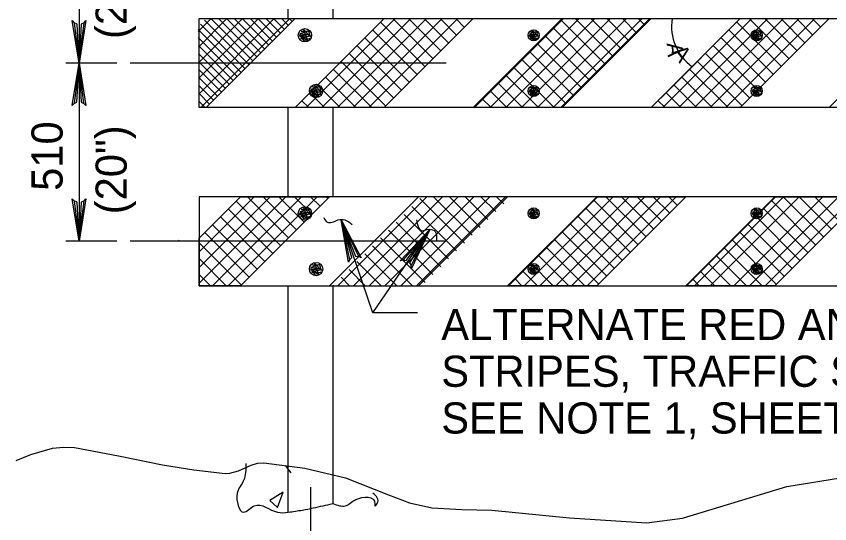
# Model space of a CAD drawing. Extents: x -4 to 901, y -468 to 720.
# Drawn here: x 91 to 178.8, y -333.9 to -279.2 of the extents above; entities that cross this region are included whole.
import ezdxf

# ---------------------------------------------------------------- set-up
doc = ezdxf.new("R2010")
doc.units = 0
doc.layers.add('2', color=7, linetype='Continuous')
doc.layers.add('3', color=7, linetype='Continuous')

msp = doc.modelspace()

# ---------------------------------------------------------------- linework, layer by layer
at = {"layer": '2'}
for p, q in [((97.81975, -265.007625), (97.81975, -284.207625)), ((110.77575, -289.007625), (110.77575, -279.407625)), ((110.77575, -279.407625), (242.46375, -279.407625)), ((111.52375, -289.007625), (121.12375, -279.407625)), ((112.21575, -279.407625), (163.21775, -279.407625)), ((121.12375, -289.007625), (130.72375, -279.407625)), ((130.72375, -289.007625), (140.32375, -279.407625)), ((140.32375, -289.007625), (149.92375, -279.407625)), ((149.92375, -289.007625), (159.52375, -279.407625)), ((159.52375, -289.007625), (169.12375, -279.407625)), ((169.12375, -289.007625), (178.72375, -279.407625)), ((178.72375, -289.007625), (188.32375, -279.407625)), ((122.47175, -281.791625), (122.05975, -280.611625)), ((122.05975, -280.611625), (122.77975, -281.381625)), ((122.77975, -281.381625), (122.56375, -280.683625)), ((147.08375, -281.693625), (146.74175, -280.709625)), ((146.74175, -280.709625), (147.34175, -281.351625)), ((171.14775, -281.693625), (170.80575, -280.709625)), ((170.80575, -280.709625), (171.40575, -281.351625)), ((122.64375, -281.099625), (121.57775, -281.301625)), ((122.08975, -281.791625), (121.57775, -281.135625)), ((121.57775, -281.135625), (122.47175, -281.791625)), ((121.57775, -281.301625), (122.76575, -281.259625)), ((122.45575, -280.761625), (121.62775, -281.043625)), ((121.62775, -281.043625), (122.64375, -281.099625)), ((122.76575, -281.259625), (121.70775, -281.583625)), ((121.70775, -281.583625), (122.68775, -281.561625)), ((121.77975, -280.761625), (122.45575, -280.761625)), ((122.68775, -281.561625), (122.08975, -281.791625)), ((122.17575, -281.207625), (122.17575, -281.207625)), ((122.77575, -281.207625), (122.77575, -281.207625)), ((147.22775, -281.117625), (146.33975, -281.285625)), ((146.76575, -281.693625), (146.33975, -281.147625)), ((146.33975, -281.147625), (147.08375, -281.693625)), ((146.33975, -281.285625), (147.32975, -281.249625)), ((147.07175, -280.835625), (146.38175, -281.069625)), ((146.38175, -281.069625), (147.22775, -281.117625)), ((147.32975, -281.249625), (146.44775, -281.519625)), ((146.44775, -281.519625), (147.26375, -281.501625)), ((146.50775, -280.835625), (147.07175, -280.835625)), ((147.26375, -281.501625), (146.76575, -281.693625)), ((146.83775, -281.207625), (146.83775, -281.207625)), ((146.83775, -281.207625), (146.83775, -281.207625)), ((147.34175, -281.351625), (147.16175, -280.769625)), ((171.29175, -281.117625), (170.40375, -281.285625)), ((170.82975, -281.693625), (170.40375, -281.147625)), ((170.40375, -281.147625), (171.14775, -281.693625)), ((170.40375, -281.285625), (171.39375, -281.249625)), ((171.13575, -280.835625), (170.44575, -281.069625)), ((170.44575, -281.069625), (171.29175, -281.117625)), ((171.39375, -281.249625), (170.51175, -281.519625)), ((170.51175, -281.519625), (171.32775, -281.501625)), ((170.57175, -280.835625), (171.13575, -280.835625)), ((171.32775, -281.501625), (170.82975, -281.693625)), ((170.90175, -281.207625), (170.90175, -281.207625)), ((170.90175, -281.207625), (170.90175, -281.207625)), ((171.40575, -281.351625), (171.22575, -280.769625)), ((101.87775, -284.207625), (96.37975, -284.207625)), ((97.81975, -284.207625), (97.81975, -303.407625)), ((137.40575, -284.207625), (103.31775, -284.207625)), ((160.54175, -287.989625), (164.94775, -283.583625)), ((123.65575, -286.761625), (122.82775, -287.043625)), ((122.97975, -286.761625), (123.65575, -286.761625)), ((123.67175, -287.791625), (123.25975, -286.611625)), ((123.25975, -286.611625), (123.97975, -287.381625)), ((123.97975, -287.381625), (123.76375, -286.683625)), ((147.07175, -286.835625), (146.38175, -287.069625)), ((146.50775, -286.835625), (147.07175, -286.835625)), ((147.08375, -287.693625), (146.74175, -286.709625)), ((146.74175, -286.709625), (147.34175, -287.351625)), ((147.34175, -287.351625), (147.16175, -286.769625)), ((171.13575, -286.835625), (170.44575, -287.069625)), ((170.57175, -286.835625), (171.13575, -286.835625)), ((171.14775, -287.693625), (170.80575, -286.709625)), ((170.80575, -286.709625), (171.40575, -287.351625)), ((171.40575, -287.351625), (171.22575, -286.769625)), ((122.77575, -287.207625), (122.77575, -287.207625)), ((123.84375, -287.099625), (122.77775, -287.301625)), ((123.28975, -287.791625), (122.77775, -287.135625)), ((122.77775, -287.135625), (123.67175, -287.791625)), ((122.77775, -287.301625), (123.96575, -287.259625)), ((122.82775, -287.043625), (123.84375, -287.099625)), ((123.96575, -287.259625), (122.90775, -287.583625)), ((122.90775, -287.583625), (123.88775, -287.561625)), ((123.88775, -287.561625), (123.28975, -287.791625)), ((123.37575, -287.207625), (123.37575, -287.207625)), ((147.22775, -287.117625), (146.33975, -287.285625)), ((146.76575, -287.693625), (146.33975, -287.147625)), ((146.33975, -287.147625), (147.08375, -287.693625)), ((146.33975, -287.285625), (147.32975, -287.249625)), ((146.38175, -287.069625), (147.22775, -287.117625)), ((147.32975, -287.249625), (146.44775, -287.519625)), ((146.44775, -287.519625), (147.26375, -287.501625)), ((147.26375, -287.501625), (146.76575, -287.693625)), ((146.83775, -287.207625), (146.83775, -287.207625)), ((146.83775, -287.207625), (146.83775, -287.207625)), ((171.29175, -287.117625), (170.40375, -287.285625)), ((170.82975, -287.693625), (170.40375, -287.147625)), ((170.40375, -287.147625), (171.14775, -287.693625)), ((170.40375, -287.285625), (171.39375, -287.249625)), ((170.44575, -287.069625), (171.29175, -287.117625)), ((171.39375, -287.249625), (170.51175, -287.519625)), ((170.51175, -287.519625), (171.32775, -287.501625)), ((171.32775, -287.501625), (170.82975, -287.693625)), ((170.90175, -287.207625), (170.90175, -287.207625)), ((170.90175, -287.207625), (170.90175, -287.207625)), ((242.2415, -289.007625), (110.77575, -289.007625)), ((110.77575, -303.069625), (115.23775, -298.607625)), ((110.77575, -298.607625), (110.77575, -308.207625)), ((242.2415, -298.607625), (110.77575, -298.607625)), ((115.23775, -308.207625), (124.83775, -298.607625)), ((124.45175, -298.995625), (124.45175, -298.995625)), ((124.83775, -308.207625), (134.43775, -298.607625)), ((134.43775, -308.207625), (144.03775, -298.607625)), ((144.03775, -308.207625), (153.63775, -298.607625)), ((153.63775, -308.207625), (163.23775, -298.607625)), ((163.23775, -308.207625), (172.83775, -298.607625)), ((172.83775, -308.207625), (182.43775, -298.607625)), ((122.45575, -299.961625), (121.62775, -300.243625)), ((121.77975, -299.961625), (122.45575, -299.961625)), ((122.47175, -300.991625), (122.05975, -299.811625)), ((122.05975, -299.811625), (122.77975, -300.581625)), ((122.77975, -300.581625), (122.56375, -299.883625)), ((123.67775, -299.767625), (123.67775, -299.767625)), ((124.06575, -299.381625), (124.06575, -299.381625)), ((147.08375, -300.893625), (146.74175, -299.909625)), ((146.74175, -299.909625), (147.34175, -300.551625)), ((147.34175, -300.551625), (147.16175, -299.969625)), ((171.14775, -300.893625), (170.80575, -299.909625)), ((170.80575, -299.909625), (171.40575, -300.551625)), ((171.40575, -300.551625), (171.22575, -299.969625)), ((122.64375, -300.299625), (121.57775, -300.501625)), ((122.08975, -300.991625), (121.57775, -300.335625)), ((121.57775, -300.335625), (122.47175, -300.991625)), ((121.57775, -300.501625), (122.76575, -300.459625)), ((121.62775, -300.243625), (122.64375, -300.299625)), ((122.76575, -300.459625), (121.70775, -300.783625)), ((121.70775, -300.783625), (122.68775, -300.761625)), ((122.68775, -300.761625), (122.08975, -300.991625)), ((122.17575, -300.407625), (122.17575, -300.407625)), ((122.77575, -300.407625), (122.77575, -300.407625)), ((122.90575, -300.539625), (122.90575, -300.539625)), ((123.29175, -300.153625), (123.29175, -300.153625)), ((147.22775, -300.317625), (146.33975, -300.485625)), ((146.76575, -300.893625), (146.33975, -300.347625)), ((146.33975, -300.347625), (147.08375, -300.893625)), ((146.33975, -300.485625), (147.32975, -300.449625)), ((147.07175, -300.035625), (146.38175, -300.269625)), ((146.38175, -300.269625), (147.22775, -300.317625)), ((147.32975, -300.449625), (146.44775, -300.719625)), ((146.44775, -300.719625), (147.26375, -300.701625)), ((146.50775, -300.035625), (147.07175, -300.035625)), ((147.26375, -300.701625), (146.76575, -300.893625)), ((146.83775, -300.407625), (146.83775, -300.407625)), ((146.83775, -300.407625), (146.83775, -300.407625)), ((171.29175, -300.317625), (170.40375, -300.485625)), ((170.82975, -300.893625), (170.40375, -300.347625)), ((170.40375, -300.347625), (171.14775, -300.893625)), ((170.40375, -300.485625), (171.39375, -300.449625)), ((171.13575, -300.035625), (170.44575, -300.269625)), ((170.44575, -300.269625), (171.29175, -300.317625)), ((171.39375, -300.449625), (170.51175, -300.719625)), ((170.51175, -300.719625), (171.32775, -300.701625)), ((170.57175, -300.035625), (171.13575, -300.035625)), ((171.32775, -300.701625), (170.82975, -300.893625)), ((170.90175, -300.407625), (170.90175, -300.407625)), ((170.90175, -300.407625), (170.90175, -300.407625)), ((101.87775, -303.407625), (96.37975, -303.407625)), ((137.40575, -303.407625), (103.31775, -303.407625)), ((123.65575, -305.961625), (122.82775, -306.243625)), ((122.97975, -305.961625), (123.65575, -305.961625)), ((123.67175, -306.991625), (123.25975, -305.811625)), ((123.25975, -305.811625), (123.97975, -306.581625)), ((123.97975, -306.581625), (123.76375, -305.883625)), ((147.07175, -306.035625), (146.38175, -306.269625)), ((146.50775, -306.035625), (147.07175, -306.035625)), ((147.08375, -306.893625), (146.74175, -305.909625)), ((146.74175, -305.909625), (147.34175, -306.551625)), ((147.34175, -306.551625), (147.16175, -305.969625)), ((171.13575, -306.035625), (170.44575, -306.269625)), ((170.57175, -306.035625), (171.13575, -306.035625)), ((171.14775, -306.893625), (170.80575, -305.909625)), ((170.80575, -305.909625), (171.40575, -306.551625)), ((171.40575, -306.551625), (171.22575, -305.969625)), ((122.77575, -306.407625), (122.77575, -306.407625)), ((123.84375, -306.299625), (122.77775, -306.501625)), ((123.28975, -306.991625), (122.77775, -306.335625)), ((122.77775, -306.335625), (123.67175, -306.991625)), ((122.77775, -306.501625), (123.96575, -306.459625)), ((122.82775, -306.243625), (123.84375, -306.299625)), ((123.96575, -306.459625), (122.90775, -306.783625)), ((122.90775, -306.783625), (123.88775, -306.761625)), ((123.88775, -306.761625), (123.28975, -306.991625)), ((123.37575, -306.407625), (123.37575, -306.407625)), ((147.22775, -306.317625), (146.33975, -306.485625)), ((146.76575, -306.893625), (146.33975, -306.347625)), ((146.33975, -306.347625), (147.08375, -306.893625)), ((146.33975, -306.485625), (147.32975, -306.449625)), ((146.38175, -306.269625), (147.22775, -306.317625)), ((147.32975, -306.449625), (146.44775, -306.719625)), ((146.44775, -306.719625), (147.26375, -306.701625)), ((147.26375, -306.701625), (146.76575, -306.893625)), ((146.83775, -306.407625), (146.83775, -306.407625)), ((146.83775, -306.407625), (146.83775, -306.407625)), ((171.29175, -306.317625), (170.40375, -306.485625)), ((170.82975, -306.893625), (170.40375, -306.347625)), ((170.40375, -306.347625), (171.14775, -306.893625)), ((170.40375, -306.485625), (171.39375, -306.449625)), ((170.44575, -306.269625), (171.29175, -306.317625)), ((171.39375, -306.449625), (170.51175, -306.719625)), ((170.51175, -306.719625), (171.32775, -306.701625)), ((171.32775, -306.701625), (170.82975, -306.893625)), ((170.90175, -306.407625), (170.90175, -306.407625)), ((170.90175, -306.407625), (170.90175, -306.407625)), ((110.77575, -308.207625), (242.2415, -308.207625)), ((120.05775, -327.595625), (120.66775, -328.391625)), ((122.77575, -329.945625), (122.77575, -358.535625))]:
    msp.add_line(p, q, dxfattribs=at)
for points in [[(120.37575, -279.407625), (120.37575, -269.807625), (125.17575, -269.807625), (125.17575, -279.407625)], [(98.36775, -279.849625), (98.05175, -280.011625), (97.81975, -284.207625), (98.36775, -279.849625), (98.55975, -279.625625), (97.81975, -284.207625), (97.61375, -280.015625), (97.30175, -279.861625), (97.81975, -284.207625), (97.09175, -279.625625), (97.30175, -279.861625)], [(110.65975, -280.813625), (112.06375, -279.407625)], [(110.68375, -282.487625), (113.76175, -279.407625)], [(110.70575, -284.159625), (115.45775, -279.407625)], [(110.72975, -285.833625), (117.15575, -279.407625)], [(110.75375, -287.507625), (118.85375, -279.407625)], [(110.94975, -289.007625), (120.54975, -279.407625)], [(116.14575, -284.385625), (111.34575, -279.585625), (111.34575, -279.585625)], [(116.56975, -283.961625), (112.01575, -279.407625)], [(116.99375, -283.537625), (112.86575, -279.407625)], [(117.41775, -283.113625), (113.71375, -279.407625)], [(117.84175, -282.689625), (114.56175, -279.407625)], [(118.26575, -282.265625), (115.40975, -279.407625)], [(118.69175, -281.841625), (116.25975, -279.407625)], [(119.11575, -281.415625), (117.10775, -279.407625)], [(119.53975, -280.991625), (117.95575, -279.407625)], [(119.96375, -280.567625), (118.80375, -279.407625)], [(120.38775, -280.143625), (119.65375, -279.407625)], [(120.81175, -279.719625), (120.50175, -279.407625)], [(122.29175, -289.007625), (131.89175, -279.407625)], [(123.98975, -289.007625), (133.58975, -279.407625)], [(125.68575, -289.007625), (135.28575, -279.407625)], [(127.38375, -289.007625), (136.98375, -279.407625)], [(129.08175, -289.007625), (138.67975, -279.407625)], [(135.14175, -284.591625), (130.34175, -279.791625)], [(135.98975, -283.741625), (131.65575, -279.407625)], [(136.83775, -282.893625), (133.35375, -279.407625)], [(137.68775, -282.045625), (135.04975, -279.409625)], [(138.53575, -281.195625), (136.74775, -279.407625)], [(139.38375, -280.347625), (138.44375, -279.407625)], [(140.23175, -279.499625), (140.14175, -279.407625)], [(140.45375, -289.007625), (150.05375, -279.407625)], [(142.15175, -289.007625), (151.75175, -279.409625)], [(143.84775, -289.007625), (153.44775, -279.407625)], [(145.54575, -289.007625), (155.14575, -279.407625)], [(147.24175, -289.007625), (156.84175, -279.407625)], [(148.93975, -289.007625), (158.53975, -279.407625)], [(154.57575, -284.355625), (149.77575, -279.555625)], [(149.78775, -289.007625), (159.38775, -279.407625)], [(155.42575, -283.507625), (151.32575, -279.407625)], [(156.27375, -282.657625), (153.02375, -279.407625)], [(157.12175, -281.809625), (154.72175, -279.407625)], [(157.96975, -280.961625), (156.41775, -279.407625)], [(158.81975, -280.113625), (158.11575, -279.407625)], [(160.78575, -289.007625), (170.38575, -279.407625)], [(162.48175, -289.007625), (172.08175, -279.407625)], [(164.17975, -289.007625), (173.77975, -279.407625)], [(165.87575, -289.007625), (175.47575, -279.407625)], [(167.57375, -289.007625), (177.17375, -279.407625)], [(173.55575, -284.575625), (168.75575, -279.775625)], [(174.40375, -283.727625), (170.08575, -279.407625)], [(175.25375, -282.877625), (171.78375, -279.407625)], [(176.10175, -282.029625), (173.47975, -279.407625)], [(176.94975, -281.181625), (175.17775, -279.407625)], [(177.79775, -280.333625), (176.87375, -279.407625)], [(178.64775, -279.483625), (178.57175, -279.407625)], [(115.29775, -285.235625), (110.65575, -280.593625)], [(115.72175, -284.809625), (110.92175, -280.009625), (110.92175, -280.009625)], [(134.29175, -285.439625), (129.49175, -280.639625)], [(153.72775, -285.203625), (148.92775, -280.403625)], [(172.70775, -285.423625), (167.90775, -280.623625)], [(114.87175, -285.659625), (110.66775, -281.455625)], [(133.44375, -286.287625), (128.64375, -281.487625)], [(152.87975, -286.051625), (148.07975, -281.251625)], [(171.85975, -286.273625), (167.05975, -281.473625)], [(114.44775, -286.083625), (110.68175, -282.315625)], [(132.59575, -287.135625), (127.79575, -282.335625)], [(152.03175, -286.901625), (147.23175, -282.101625)], [(171.00975, -287.121625), (166.20975, -282.321625)], [(114.02375, -286.507625), (110.69375, -283.175625)], [(131.74775, -287.985625), (126.94775, -283.185625)], [(151.18175, -287.749625), (146.38175, -282.949625)], [(170.16175, -287.969625), (165.36175, -283.169625)], [(97.27375, -288.567625), (97.58975, -288.405625), (97.81975, -284.207625), (97.27375, -288.567625), (97.08175, -288.791625), (97.81975, -284.207625), (98.02775, -288.401625), (98.33975, -288.555625), (97.81975, -284.207625), (98.54975, -288.791625), (98.33975, -288.555625)], [(113.59975, -286.931625), (110.70575, -284.037625)], [(130.89775, -288.833625), (126.09775, -284.033625)], [(150.33375, -288.597625), (145.53375, -283.797625)], [(169.31375, -288.817625), (164.51375, -284.017625)], [(113.17575, -287.355625), (110.71775, -284.897625)], [(129.37775, -289.007625), (125.24975, -284.881625)], [(149.04775, -289.007625), (144.68575, -284.645625)], [(167.80575, -289.007625), (163.66575, -284.867625)], [(112.75175, -287.779625), (110.72975, -285.759625)], [(127.67975, -289.007625), (124.40175, -285.729625)], [(147.34975, -289.007625), (143.83775, -285.495625)], [(166.10975, -289.007625), (162.81575, -285.715625)], [(112.32775, -288.203625), (110.74175, -286.619625)], [(125.98175, -289.007625), (123.55375, -286.579625)], [(145.65375, -289.007625), (142.98775, -286.343625)], [(164.41175, -289.007625), (161.96775, -286.563625)], [(111.90175, -288.629625), (110.75375, -287.479625)], [(124.28575, -289.007625), (122.70375, -287.427625)], [(143.95575, -289.007625), (142.13975, -287.191625)], [(162.71575, -289.007625), (161.11975, -287.411625)], [(111.43375, -289.007625), (110.76575, -288.341625)], [(122.58775, -289.007625), (121.85575, -288.275625)], [(142.25975, -289.007625), (141.29175, -288.041625)], [(161.01775, -289.007625), (160.27175, -288.261625)], [(120.37575, -298.607625), (120.37575, -289.007625)], [(125.17575, -289.007625), (125.17575, -298.607625)], [(140.56175, -289.007625), (140.44175, -288.889625)], [(98.36775, -299.049625), (98.05175, -299.211625), (97.81975, -303.407625), (98.36775, -299.049625), (98.55975, -298.825625), (97.81975, -303.407625), (97.61375, -299.215625), (97.30175, -299.061625), (97.81975, -303.407625), (97.09175, -298.825625), (97.30175, -299.061625)], [(110.77575, -307.941625), (120.10775, -298.607625)], [(110.77575, -306.243625), (118.41175, -298.607625)], [(110.77575, -304.547625), (116.71375, -298.607625)], [(112.20575, -308.207625), (121.80575, -298.607625)], [(113.90375, -308.207625), (123.50175, -298.607625)], [(119.55775, -303.887625), (114.75775, -299.087625)], [(120.40775, -303.039625), (115.97575, -298.607625)], [(121.25575, -302.189625), (117.67375, -298.607625)], [(122.10375, -301.341625), (119.36975, -298.607625)], [(122.95175, -300.493625), (121.06775, -298.607625)], [(123.80175, -299.645625), (122.76575, -298.607625)], [(124.64975, -298.795625), (124.46175, -298.607625)], [(125.71575, -308.207625), (135.31575, -298.607625)], [(127.41375, -308.207625), (137.01375, -298.607625)], [(129.10975, -308.207625), (138.70975, -298.607625)], [(130.80775, -308.207625), (140.40775, -298.607625)], [(132.50375, -308.207625), (142.10375, -298.607625)], [(134.20175, -308.207625), (143.80175, -298.607625)], [(139.36775, -303.617625), (134.56775, -298.817625)], [(140.21575, -302.767625), (136.05575, -298.607625)], [(141.06375, -301.919625), (137.75375, -298.607625)], [(141.91375, -301.071625), (139.44975, -298.607625)], [(142.76175, -300.221625), (141.14775, -298.607625)], [(143.60975, -299.373625), (142.84375, -298.607625)], [(144.12975, -308.207625), (153.72975, -298.607625)], [(145.82775, -308.207625), (155.42775, -298.607625)], [(147.52375, -308.207625), (157.12375, -298.607625)], [(149.22175, -308.207625), (158.82175, -298.607625)], [(150.91775, -308.207625), (160.51775, -298.607625)], [(152.61575, -308.207625), (162.21575, -298.607625)], [(158.08375, -303.761625), (153.28375, -298.961625)], [(158.93175, -302.913625), (154.62775, -298.607625)], [(159.77975, -302.065625), (156.32375, -298.607625)], [(160.62975, -301.215625), (158.02175, -298.607625)], [(161.47775, -300.367625), (159.71775, -298.607625)], [(162.32575, -299.519625), (161.41575, -298.607625)], [(163.17575, -298.671625), (163.11175, -298.607625)], [(163.32975, -308.207625), (172.92975, -298.607625)], [(164.17775, -308.207625), (173.77775, -298.607625)], [(165.87575, -308.207625), (175.47575, -298.607625)], [(168.41975, -308.207625), (178.01975, -298.607625)], [(170.11775, -308.207625), (179.71775, -298.607625)], [(171.81375, -308.207625), (181.41375, -298.607625)], [(177.25175, -303.793625), (172.45175, -298.993625)], [(178.09975, -302.945625), (173.76375, -298.607625)], [(178.94975, -302.097625), (175.46175, -298.607625)], [(179.79775, -301.247625), (177.15775, -298.607625)], [(118.70975, -304.735625), (113.90975, -299.935625)], [(138.51975, -304.465625), (133.71975, -299.665625)], [(157.23575, -304.609625), (152.43575, -299.811625)], [(176.40375, -304.641625), (171.60375, -299.841625)], [(117.86175, -305.585625), (113.06175, -300.785625)], [(137.66975, -305.313625), (132.86975, -300.513625)], [(156.38575, -305.459625), (151.58575, -300.659625)], [(175.55575, -305.491625), (170.75575, -300.691625)], [(117.01175, -306.433625), (112.21175, -301.633625)], [(134.31575, -311.117625), (129.51575, -311.117625), (126.08175, -301.111625)], [(126.97975, -305.413625), (127.22575, -305.157625), (126.08175, -301.111625), (126.97975, -305.413625), (126.87175, -305.687625), (126.08175, -301.111625), (127.63975, -305.011625), (127.98375, -305.055625), (126.08175, -301.111625), (128.25775, -305.211625), (127.98375, -305.055625)], [(136.82175, -306.161625), (132.02175, -301.361625)], [(155.53775, -306.307625), (150.73775, -301.507625)], [(174.70575, -306.339625), (169.90575, -301.539625)], [(116.16375, -307.281625), (111.36375, -302.481625)], [(129.51575, -311.117625), (135.65775, -302.149625)], [(135.97375, -307.011625), (131.17375, -302.211625)], [(132.74175, -305.437625), (133.09375, -305.481625), (135.65775, -302.149625), (132.74175, -305.437625), (132.45775, -305.513625), (135.65775, -302.149625), (133.45775, -305.725625), (133.62975, -306.029625), (135.65775, -302.149625), (133.66775, -306.341625), (133.62975, -306.029625)], [(154.68975, -307.155625), (149.88975, -302.355625)], [(173.85775, -307.187625), (169.05775, -302.387625)], [(108.64775, -303.401625), (108.52775, -303.281625)], [(135.12575, -307.859625), (130.32575, -303.059625)], [(153.84175, -308.005625), (149.04175, -303.205625)], [(173.00975, -308.035625), (168.20975, -303.235625)], [(115.31575, -308.129625), (110.77575, -303.589625)], [(133.77775, -308.207625), (129.47575, -303.907625)], [(152.34775, -308.207625), (148.19175, -304.053625)], [(171.48375, -308.207625), (167.36175, -304.085625)], [(132.07975, -308.207625), (128.62775, -304.757625)], [(150.64975, -308.207625), (147.34375, -304.901625)], [(169.78775, -308.207625), (166.51175, -304.933625)], [(113.69775, -308.207625), (110.77575, -305.287625)], [(130.38375, -308.207625), (127.77975, -305.605625)], [(148.95375, -308.207625), (146.49575, -305.749625)], [(168.08975, -308.207625), (165.66375, -305.781625)], [(111.99975, -308.207625), (110.77575, -306.983625)], [(128.68575, -308.207625), (126.93175, -306.453625)], [(147.25575, -308.207625), (145.64775, -306.599625)], [(166.39375, -308.207625), (164.81575, -306.629625)], [(126.98975, -308.207625), (126.08175, -307.301625)], [(145.55975, -308.207625), (144.79775, -307.447625)], [(164.69575, -308.207625), (163.96775, -307.479625)], [(120.37575, -332.633625), (120.37575, -308.207625)], [(125.17575, -308.207625), (125.17575, -331.703625)], [(125.29175, -308.207625), (125.23375, -308.151625)], [(91.04575, -327.061625), (92.60775, -326.417625), (94.95575, -325.743625), (96.13175, -325.613625), (97.31175, -325.669625), (102.06975, -326.559625), (106.82975, -327.525625), (110.19575, -328.051625), (113.56175, -328.453625), (114.09175, -328.439625), (115.00775, -328.175625), (116.36975, -327.577625), (117.05175, -327.355625), (117.73975, -327.293625), (122.14775, -327.869625), (126.55975, -328.919625), (131.17575, -330.745625), (133.46575, -331.637625), (135.84575, -332.169625), (139.09375, -332.323625), (142.34575, -332.401625), (150.71175, -333.251625), (159.05975, -333.793625), (162.87575, -333.269625), (174.14775, -329.847625), (179.93775, -328.927625)]]:
    msp.add_lwpolyline(points, dxfattribs=at)
for points in [[(121.12375, -289.007625), (130.72375, -279.407625), (140.32375, -279.407625), (130.72375, -289.007625)], [(140.32375, -289.007625), (149.92375, -279.407625), (159.52375, -279.407625), (149.92375, -289.007625)], [(159.52375, -289.007625), (169.12375, -279.407625), (178.72375, -279.407625), (169.12375, -289.007625)], [(110.77575, -303.069625), (115.23775, -298.607625), (124.83775, -298.607625), (115.23775, -308.207625), (110.77575, -308.207625)], [(144.03775, -308.207625), (153.63775, -298.607625), (163.23775, -298.607625), (153.63775, -308.207625)], [(163.23775, -308.207625), (172.83775, -298.607625), (182.43775, -298.607625), (172.83775, -308.207625)], [(119.83975, -330.479625), (118.39975, -331.379625), (119.21575, -332.111625)]]:
    msp.add_lwpolyline(points, close=True, dxfattribs=at)
for centre, radius in [((122.17589, -281.208528), 0.72), ((146.83853, -281.208528), 0.6), ((170.90141, -281.208528), 0.6), ((123.37589, -287.208528), 0.72), ((146.83853, -287.208528), 0.6), ((170.90141, -287.208528), 0.6), ((122.17589, -300.408528), 0.72), ((146.83853, -300.408528), 0.6), ((170.90141, -300.408528), 0.6), ((123.37589, -306.408528), 0.72), ((146.83853, -306.408528), 0.6), ((170.90141, -306.408528), 0.6)]:
    msp.add_circle(centre, radius, dxfattribs=at)
msp.add_arc((167.103012, -280.245235), 5.390059, 171.06977778, 233.93211667, dxfattribs=at)
for points in [[(124.21975, -300.859625), (124.59775, -301.365625), (125.10375, -301.365625), (125.73575, -301.111625), (126.49375, -301.111625), (127.25175, -301.617625)], [(134.20175, -301.111625), (134.32775, -301.617625), (134.70775, -302.249625), (135.59175, -302.123625), (136.22375, -302.375625), (136.34975, -303.387625)], [(115.79375, -327.383625), (115.56375, -329.209625), (114.87975, -330.581625), (115.57575, -332.633625), (116.70575, -331.951625), (119.21775, -332.635625), (120.37575, -332.633625)], [(125.17575, -331.703625), (126.52575, -331.951625), (127.66775, -331.265625), (129.72375, -331.723625), (129.72375, -331.951625), (129.97575, -331.703625), (129.49575, -330.581625)], [(120.37575, -332.633625), (121.91775, -332.401625), (123.07775, -332.169625), (125.17575, -331.703625)]]:
    msp.add_spline(points, degree=3, dxfattribs=at)

# ---------------------------------------------------------------- texts
for height, rotation, p in [(1.727796, 275.64735556, (161.17375, -282.071625)), (1.727688, 307.48319722, (161.66575, -283.071625))]:
    msp.add_text('A', height=height, rotation=rotation, dxfattribs=at).set_placement(p)
at = {"layer": '3'}
for s, p in [('(20")', (102.9595, -281.607625)), ('510', (96.04325, -297.980625)), ('(20")', (102.95925, -300.506625))]:
    msp.add_text(s, height=3.36, rotation=90, dxfattribs=at).set_placement(p)
for s, p in [('ALTERNATE RED AND WHITE', (136.87975, -314.071625)), ('STRIPES, TRAFFIC SIDE ONLY,', (136.87975, -319.111625)), ('SEE NOTE 1, SHEET 1.', (136.87975, -324.151625))]:
    msp.add_text(s, height=3.359988, dxfattribs=at).set_placement(p)

doc.saveas('drawing.dxf')
